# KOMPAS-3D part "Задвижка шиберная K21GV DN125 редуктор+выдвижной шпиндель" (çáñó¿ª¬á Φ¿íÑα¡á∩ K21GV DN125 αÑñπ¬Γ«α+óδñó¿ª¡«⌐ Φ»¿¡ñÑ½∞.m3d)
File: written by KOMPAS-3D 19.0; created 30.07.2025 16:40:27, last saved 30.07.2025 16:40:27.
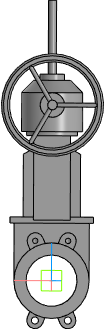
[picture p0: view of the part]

Document properties: Полное имя файла: Задвижка шиберная K21GV DN125 редуктор+выдвижной шпиндель.a3d

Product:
- Part/product: Задвижка шиберная K21GV DN125 редуктор+выдвижной шпиндель
    Масса: 34.8152

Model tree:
1. Операция без истории:1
